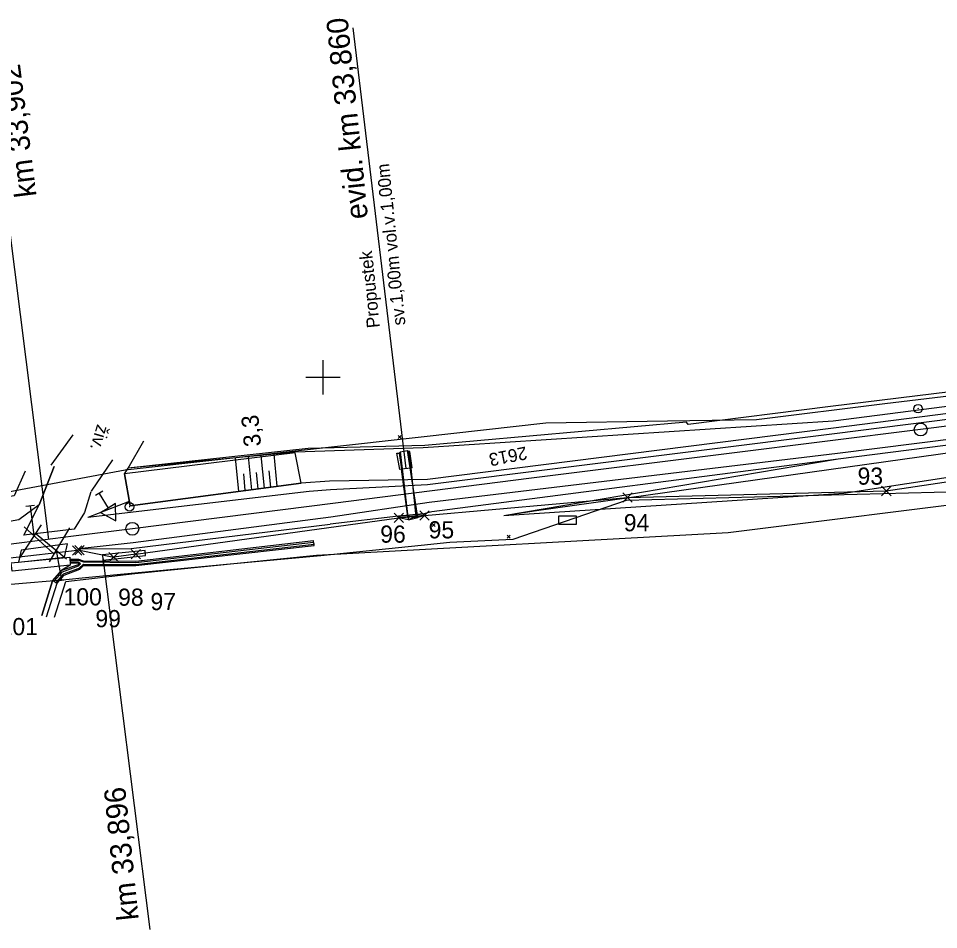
# Model space of a CAD drawing. Extents: x -805011 to -803920, y -1150790 to -1150234.
# Drawn here: x -804735.5 to -804628.3, y -1150564.4 to -1150458.2 of the extents above; entities that cross this region are included whole.
import ezdxf

# ---------------------------------------------------------------- set-up
doc = ezdxf.new("R2010")
doc.units = 0
for name, color, linetype in [('0381KM032-037P - Vrstva 1', 7, 'Continuous'), ('0381KM032-037P - Vrstva 13', 7, 'Continuous'), ('0381KM032-037P - Vrstva 17', 7, 'Continuous'), ('0381KM032-037P - Vrstva 19', 7, 'Continuous'), ('0381KM032-037P - Vrstva 25', 7, 'Continuous'), ('0381KM032-037P - Vrstva 4', 7, 'Continuous'), ('0381KM032-037P - Vrstva 43', 7, 'Continuous'), ('0381KM032-037P - Vrstva 48', 7, 'Continuous'), ('0381KM032-037P - Vrstva 49', 7, 'Continuous'), ('0381KM032-037P - Vrstva 51', 7, 'Continuous'), ('0381KM032-037P - Vrstva 57', 7, 'Continuous'), ('0381KM032-037P - Vrstva 7', 7, 'Continuous'), ('0381KM032-037P - Vrstva 9', 7, 'Continuous'), ('Default', 7, 'Continuous'), ('hran DP - hran DP', 7, 'Continuous'), ('krizky_1000 - Vrstva 1', 7, 'Continuous'), ('PSR_C2_2_Lomove_body_Vimperk - Vrstva 60', 7, 'Continuous'), ('PSR_C2_2_trasa_Vimperk - Kabelová trasa', 7, 'Continuous')]:
    doc.layers.add(name, color=color, linetype=linetype)

msp = doc.modelspace()

# ---------------------------------------------------------------- linework, layer by layer
at = {"layer": '0381KM032-037P - Vrstva 1'}
msp.add_lwpolyline([(-804485.9, -1150487.74), (-804508.11, -1150490.55), (-804529.67, -1150493.3), (-804537.63, -1150494.31), (-804546.61, -1150495.46), (-804554.2, -1150496.42), (-804564.05, -1150497.67), (-804586.01, -1150500.48), (-804607.92, -1150503.26), (-804630.35, -1150506.11), (-804652.65, -1150508.9), (-804675.7, -1150511.78), (-804698.85, -1150514.71), (-804701.61, -1150515.06), (-804722.18, -1150517.67), (-804729.05, -1150518.54), (-804735.1, -1150519.31), (-804744.56, -1150520.5), (-804767.65, -1150523.46), (-804791, -1150526.42)], dxfattribs=at)
at = {"layer": '0381KM032-037P - Vrstva 13'}
for points in [[(-804703.22, -1150508.8), (-804723.12, -1150511.26), (-804722.46, -1150514.99), (-804702.53, -1150512.35), (-804703.22, -1150508.8)], [(-804732.2, -1150527.92), (-804730.97, -1150524.01), (-804730.13, -1150523.06), (-804728.33, -1150522.36), (-804727.9, -1150521.95), (-804721.78, -1150521.96), (-804701.01, -1150519.63), (-804701.03, -1150519.46), (-804701.1, -1150519.22), (-804701.1, -1150519.05)], [(-804731.12, -1150523.92), (-804730.21, -1150522.94), (-804728.39, -1150522.25), (-804727.91, -1150521.81), (-804721.79, -1150521.85), (-804701.03, -1150519.46)], [(-804729.45, -1150521.32), (-804728.46, -1150521.31), (-804727.91, -1150521.54), (-804721.8, -1150521.59), (-804701.1, -1150519.22)], [(-804729.38, -1150521.22), (-804728.48, -1150521.2), (-804727.92, -1150521.41), (-804721.8, -1150521.43), (-804701.1, -1150519.05)], [(-804732.74, -1150527.78), (-804731.51, -1150523.73), (-804730.41, -1150522.51), (-804728.49, -1150521.85), (-804728.25, -1150521.76), (-804728.53, -1150521.71), (-804729.44, -1150521.68)], [(-804731.32, -1150523.78), (-804730.35, -1150522.68), (-804728.48, -1150521.99), (-804728.25, -1150521.76), (-804728.5, -1150521.58), (-804729.42, -1150521.57)], [(-804729.38, -1150521.22), (-804729.45, -1150521.32), (-804729.42, -1150521.57), (-804729.44, -1150521.68)], [(-804731.51, -1150523.73), (-804731.32, -1150523.78), (-804731.12, -1150523.92), (-804730.97, -1150524.01)]]:
    msp.add_lwpolyline(points, dxfattribs=at)
at = {"layer": '0381KM032-037P - Vrstva 17'}
for p, q in [((-804731.66, -1150510.27), (-804729.1, -1150506.73)), ((-804726.96, -1150513.28), (-804724.46, -1150509.62))]:
    msp.add_line(p, q, dxfattribs=at)
for points in [[(-804552.89, -1150488.84), (-804553.29, -1150492.03), (-804593.3, -1150497.6), (-804640.86, -1150503.43), (-804657.42, -1150505.51), (-804657.62, -1150505.23), (-804688.14, -1150507.97), (-804701.71, -1150508.32), (-804722.68, -1150510.59), (-804720.85, -1150507.4)], [(-804731.29, -1150527.98), (-804729.95, -1150523.81), (-804721.9, -1150522.89), (-804700.75, -1150520.73), (-804652.77, -1150518.11), (-804588.21, -1150510.02), (-804572.8, -1150507.15), (-804561.55, -1150507.7), (-804553.92, -1150509.55)], [(-804734.71, -1150510.96), (-804735.96, -1150513.84), (-804741.77, -1150514.83), (-804760.36, -1150517.2), (-804793.92, -1150520.9)]]:
    msp.add_lwpolyline(points, dxfattribs=at)
at = {"layer": '0381KM032-037P - Vrstva 19'}
for p, q in [((-804690.3, -1150510.66), (-804696.47, -1150459.27)), ((-804690.02, -1150516.61), (-804690.96, -1150508.7)), ((-804688.92, -1150516.37), (-804690.16, -1150508.54)), ((-804690.09, -1150516.25), (-804690.83, -1150510.72)), ((-804689.77, -1150510.59), (-804689.19, -1150516.28)), ((-804690.02, -1150516.61), (-804688.92, -1150516.37))]:
    msp.add_line(p, q, dxfattribs=at)
for points in [[(-804689.58, -1150510.57), (-804689.77, -1150510.59), (-804690.83, -1150510.72), (-804691.04, -1150510.74), (-804691.4, -1150508.85), (-804691.12, -1150508.86), (-804690.83, -1150510.72)], [(-804691.12, -1150508.86), (-804690.96, -1150508.7), (-804690.59, -1150508.62), (-804690.16, -1150508.54), (-804690.08, -1150508.63)], [(-804689.58, -1150510.57), (-804689.88, -1150508.68), (-804690.08, -1150508.63), (-804689.77, -1150510.59)], [(-804688.16, -1150516.11), (-804688.92, -1150516.37), (-804689.19, -1150516.28), (-804690.09, -1150516.25), (-804690.02, -1150516.61), (-804691.14, -1150516.38)]]:
    msp.add_lwpolyline(points, dxfattribs=at)
msp.add_lwpolyline([(-804688.22, -1150515.92), (-804688.16, -1150516.11), (-804691.14, -1150516.38), (-804691.19, -1150516.18)], close=True, dxfattribs=at)
at = {"layer": '0381KM032-037P - Vrstva 25'}
msp.add_lwpolyline([(-804672.5, -1150517.17), (-804672.5, -1150516.17), (-804670.5, -1150516.17), (-804670.5, -1150517.17), (-804672.5, -1150517.17)], dxfattribs=at)
at = {"layer": '0381KM032-037P - Vrstva 4'}
for p, q in [((-804738.68, -1150465.82), (-804731.99, -1150518.9)), ((-804699.22, -1150512.12), (-804702.53, -1150512.35)), ((-804733.62, -1150514.94), (-804734.61, -1150515.06)), ((-804734.11, -1150515), (-804733.68, -1150518.47)), ((-804691.19, -1150516.18), (-804699.14, -1150517.12)), ((-804688.22, -1150515.92), (-804691.19, -1150516.18)), ((-804732.83, -1150517.21), (-804735.37, -1150521.05)), ((-804731.4, -1150520.55), (-804734.81, -1150517.46)), ((-804731.84, -1150521.52), (-804729.49, -1150517.55)), ((-804729.05, -1150518.54), (-804735.1, -1150519.31)), ((-804733.43, -1150518.25), (-804729.87, -1150521.17)), ((-804730.44, -1150523.66), (-804731.05, -1150520.21)), ((-804730.93, -1150523.75), (-804729.95, -1150523.57))]:
    msp.add_line(p, q, dxfattribs=at)
for points in [[(-804593.11, -1150499.86), (-804640.49, -1150505.94), (-804687.8, -1150511.91), (-804699.22, -1150512.12)], [(-804593.19, -1150500.62), (-804640.38, -1150506.6), (-804687.82, -1150512.54), (-804699.1, -1150513.12)], [(-804592.89, -1150502.96), (-804640.05, -1150508.88), (-804687.61, -1150514.59), (-804699.07, -1150516.32)], [(-804592.67, -1150503.55), (-804639.94, -1150509.55), (-804687.3, -1150515.71), (-804688.22, -1150515.92)], [(-804702.53, -1150512.35), (-804722.46, -1150514.99), (-804722.57, -1150514.49)], [(-804699.1, -1150513.12), (-804701.6, -1150513.32), (-804727.4, -1150516.37)], [(-804722.57, -1150514.49), (-804727.4, -1150516.37)], [(-804699.07, -1150516.32), (-804722.12, -1150519.29), (-804728.4, -1150520.02), (-804722.36, -1150519.97), (-804699.14, -1150517.12)]]:
    msp.add_lwpolyline(points, dxfattribs=at)
at = {"layer": '0381KM032-037P - Vrstva 43'}
msp.add_lwpolyline([(-804736.33, -1150521.65), (-804729.5, -1150520.98), (-804729.45, -1150521.92), (-804736.22, -1150522.62)], close=True, dxfattribs=at)
at = {"layer": '0381KM032-037P - Vrstva 48'}
for p, q in [((-804706.81, -1150512.92), (-804707.19, -1150509.11)), ((-804705.32, -1150512.72), (-804705.69, -1150508.97)), ((-804709.78, -1150513.31), (-804710.17, -1150509.4)), ((-804708.29, -1150513.12), (-804708.68, -1150509.26)), ((-804709.04, -1150513.21), (-804709.23, -1150511.27)), ((-804707.55, -1150513.02), (-804707.74, -1150511.1)), ((-804706.06, -1150512.82), (-804706.25, -1150510.93))]:
    msp.add_line(p, q, dxfattribs=at)
at = {"layer": '0381KM032-037P - Vrstva 49'}
for p, q in [((-804690.87, -1150506.79), (-804691.22, -1150507.14)), ((-804691.22, -1150506.79), (-804690.87, -1150507.14)), ((-804686.9, -1150517.05), (-804687.25, -1150517.41)), ((-804687.25, -1150517.05), (-804686.9, -1150517.41)), ((-804678.19, -1150518.41), (-804678.54, -1150518.76)), ((-804678.54, -1150518.41), (-804678.19, -1150518.76))]:
    msp.add_line(p, q, dxfattribs=at)
for points in [[(-804554.49, -1150494.02), (-804593.21, -1150499.01), (-804640.53, -1150505.12), (-804688.31, -1150508.22), (-804703.24, -1150508.74), (-804722.68, -1150510.59)], [(-804544.42, -1150497.94), (-804556.65, -1150501.33), (-804579.48, -1150502.32), (-804589.81, -1150503.62), (-804675.11, -1150515.57), (-804678.92, -1150516.15)], [(-804544.42, -1150497.94), (-804557.28, -1150504.11), (-804579.29, -1150503.91), (-804588.92, -1150505.83), (-804639.29, -1150513.56), (-804678.92, -1150516.15)], [(-804556.53, -1150499.44), (-804592.67, -1150503.55), (-804639.94, -1150509.55), (-804678.92, -1150516.15)], [(-804593.11, -1150499.86), (-804640.49, -1150505.94), (-804687.8, -1150511.91), (-804699.22, -1150512.12)], [(-804731.33, -1150510.42), (-804733.06, -1150514.89), (-804735.43, -1150516.61), (-804744.9, -1150518.34), (-804767.83, -1150521.26), (-804794.61, -1150523.51)], [(-804722.46, -1150514.99), (-804723.12, -1150511.26), (-804722.68, -1150510.59)], [(-804699.22, -1150512.12), (-804702.53, -1150512.35), (-804722.46, -1150514.99)], [(-804690.02, -1150516.61), (-804688.92, -1150516.37), (-804689.47, -1150516.35), (-804690.02, -1150516.61)]]:
    msp.add_lwpolyline(points, dxfattribs=at)
at = {"layer": '0381KM032-037P - Vrstva 51'}
msp.add_line((-804725.64, -1150513.28), (-804726.5, -1150513.8), dxfattribs=at)
for points in [[(-804727.06, -1150513.38), (-804727.78, -1150515.77), (-804729, -1150517.7), (-804734.83, -1150518.42), (-804733.06, -1150514.89), (-804731.33, -1150510.42)], [(-804726.07, -1150513.54), (-804725.04, -1150515.25), (-804725.9, -1150515.77), (-804724.14, -1150516.75), (-804724.18, -1150514.73), (-804725.04, -1150515.25)], [(-804729.45, -1150521.92), (-804730.41, -1150522.51), (-804731.51, -1150523.73), (-804732.74, -1150527.78)]]:
    msp.add_lwpolyline(points, dxfattribs=at)
msp.add_lwpolyline([(-804730.11, -1150520.97), (-804729.76, -1150519.41), (-804735.16, -1150520.17), (-804735.48, -1150521.58)], close=True, dxfattribs=at)
at = {"layer": '0381KM032-037P - Vrstva 7'}
for p, q in [((-804630.6, -1150503.66), (-804630.7, -1150503.68)), ((-804722.48, -1150515.11), (-804722.58, -1150515.12))]:
    msp.add_line(p, q, dxfattribs=at)
for centre, radius in [((-804630.65, -1150503.67), 0.5), ((-804630.34, -1150506.1), 0.75), ((-804722.53, -1150515.12), 0.5), ((-804722.2, -1150517.67), 0.75)]:
    msp.add_circle(centre, radius, dxfattribs=at)
at = {"layer": '0381KM032-037P - Vrstva 9'}
for p, q in [((-804720.72, -1150520.2), (-804725.69, -1150520.71)), ((-804725.69, -1150520.71), (-804725.63, -1150521.31)), ((-804725.66, -1150521.01), (-804720.15, -1150564.39)), ((-804725.63, -1150521.31), (-804720.66, -1150520.79)), ((-804720.66, -1150520.79), (-804720.72, -1150520.2)), ((-804725.63, -1150521.31), (-804725.57, -1150521.9))]:
    msp.add_line(p, q, dxfattribs=at)
at = {"layer": 'hran DP - hran DP'}
for p, q in [((-804634.52, -1150503.07), (-804621.33, -1150501.45)), ((-804649.49, -1150504.92), (-804634.52, -1150503.07)), ((-804659.84, -1150505.09), (-804649.49, -1150504.92)), ((-804688.55, -1150506.95), (-804674.03, -1150505.33)), ((-804674.03, -1150505.33), (-804659.84, -1150505.09)), ((-804723.03, -1150510.78), (-804688.55, -1150506.95)), ((-804747.72, -1150515.43), (-804723.03, -1150510.78)), ((-804621.63, -1150513.27), (-804664.68, -1150514.39)), ((-804664.68, -1150514.39), (-804677.85, -1150518.93)), ((-804688.56, -1150519.6), (-804700.23, -1150520.83)), ((-804685.22, -1150519.25), (-804688.56, -1150519.6)), ((-804677.85, -1150518.93), (-804685.22, -1150519.25)), ((-804700.23, -1150520.83), (-804710.79, -1150521.81)), ((-804710.79, -1150521.81), (-804727.28, -1150523.34)), ((-804729.97, -1150523.63), (-804736.36, -1150524.18)), ((-804727.28, -1150523.34), (-804729.97, -1150523.63))]:
    msp.add_line(p, q, dxfattribs=at)
at = {"layer": 'krizky_1000 - Vrstva 1'}
for points in [[(-804700, -1150498), (-804700, -1150502)], [(-804702, -1150500), (-804698, -1150500)]]:
    msp.add_lwpolyline(points, dxfattribs=at)
at = {"layer": 'PSR_C2_2_Lomove_body_Vimperk - Vrstva 60'}
for p, q in [((-804665.05, -1150514.56), (-804663.95, -1150513.46)), ((-804663.95, -1150514.56), (-804665.05, -1150513.46)), ((-804634.9, -1150513.81), (-804633.8, -1150512.71)), ((-804633.8, -1150513.81), (-804634.9, -1150512.71)), ((-804688.71, -1150516.66), (-804687.61, -1150515.56)), ((-804687.61, -1150516.66), (-804688.71, -1150515.56)), ((-804691.69, -1150516.93), (-804690.59, -1150515.83)), ((-804690.59, -1150516.93), (-804691.69, -1150515.83)), ((-804729.19, -1150520.75), (-804728.09, -1150519.65)), ((-804728.09, -1150520.75), (-804729.19, -1150519.65)), ((-804728.91, -1150520.72), (-804727.81, -1150519.62)), ((-804727.81, -1150520.72), (-804728.91, -1150519.62)), ((-804724.93, -1150521.52), (-804723.83, -1150520.42)), ((-804723.83, -1150521.52), (-804724.93, -1150520.42)), ((-804722.35, -1150521.19), (-804721.25, -1150520.09)), ((-804721.25, -1150521.19), (-804722.35, -1150520.09))]:
    msp.add_line(p, q, dxfattribs=at)
at = {"layer": 'PSR_C2_2_trasa_Vimperk - Kabelová trasa'}
for p, q in [((-804634.35, -1150513.26), (-804617.64, -1150510.74)), ((-804664.5, -1150514.01), (-804634.35, -1150513.26)), ((-804688.16, -1150516.11), (-804664.5, -1150514.01)), ((-804721.8, -1150520.64), (-804691.14, -1150516.38)), ((-804691.14, -1150516.38), (-804688.16, -1150516.11)), ((-804728.64, -1150520.2), (-804736.74, -1150521.15)), ((-804728.36, -1150520.17), (-804724.38, -1150520.97)), ((-804721.8, -1150520.64), (-804724.38, -1150520.97))]:
    msp.add_line(p, q, dxfattribs=at)

# ---------------------------------------------------------------- texts
at = {"layer": '0381KM032-037P - Vrstva 19'}
for s, height, p in [('evid. km 33,860', 2.5, (-804694.74, -1150481.46)), ('sv.1,00m vol.v.1,00m', 1.5, (-804690.37, -1150493.89)), ('Propustek', 1.5, (-804693.36, -1150494.19))]:
    msp.add_text(s, height=height, rotation=95.8316, dxfattribs=at).set_placement(p)
at = {"layer": '0381KM032-037P - Vrstva 4'}
msp.add_text('km 33,902', height=2.5, rotation=97.1938, dxfattribs=at).set_placement((-804733.36, -1150478.88))
at = {"layer": '0381KM032-037P - Vrstva 48'}
msp.add_text('3,3', height=2, rotation=95.4373, dxfattribs=at).set_placement((-804707.19, -1150508.01))
at = {"layer": '0381KM032-037P - Vrstva 51'}
msp.add_text('živ.', height=1.5, rotation=253.3622, dxfattribs=at).set_placement((-804726.29, -1150505.42))
at = {"layer": '0381KM032-037P - Vrstva 57'}
msp.add_text('2613', height=1.5, rotation=191.1139, dxfattribs=at).set_placement((-804676.37, -1150508.07))
at = {"layer": '0381KM032-037P - Vrstva 9'}
msp.add_text('km 33,896', height=2.5, rotation=95.8904, dxfattribs=at).set_placement((-804721.45, -1150563.2))
at = {"layer": 'Default'}
for s, p in [('93', (-804637.7, -1150512.53)), ('94', (-804664.94, -1150517.96)), ('96', (-804693.32, -1150519.29)), ('95', (-804687.68, -1150518.79)), ('100', (-804730.22, -1150526.6)), ('98', (-804723.86, -1150526.64)), ('97', (-804720.09, -1150527.15)), ('99', (-804726.51, -1150529.14)), ('101', (-804737.67, -1150530.07))]:
    msp.add_text(s, height=2, dxfattribs=at).set_placement(p)

doc.saveas('drawing.dxf')
